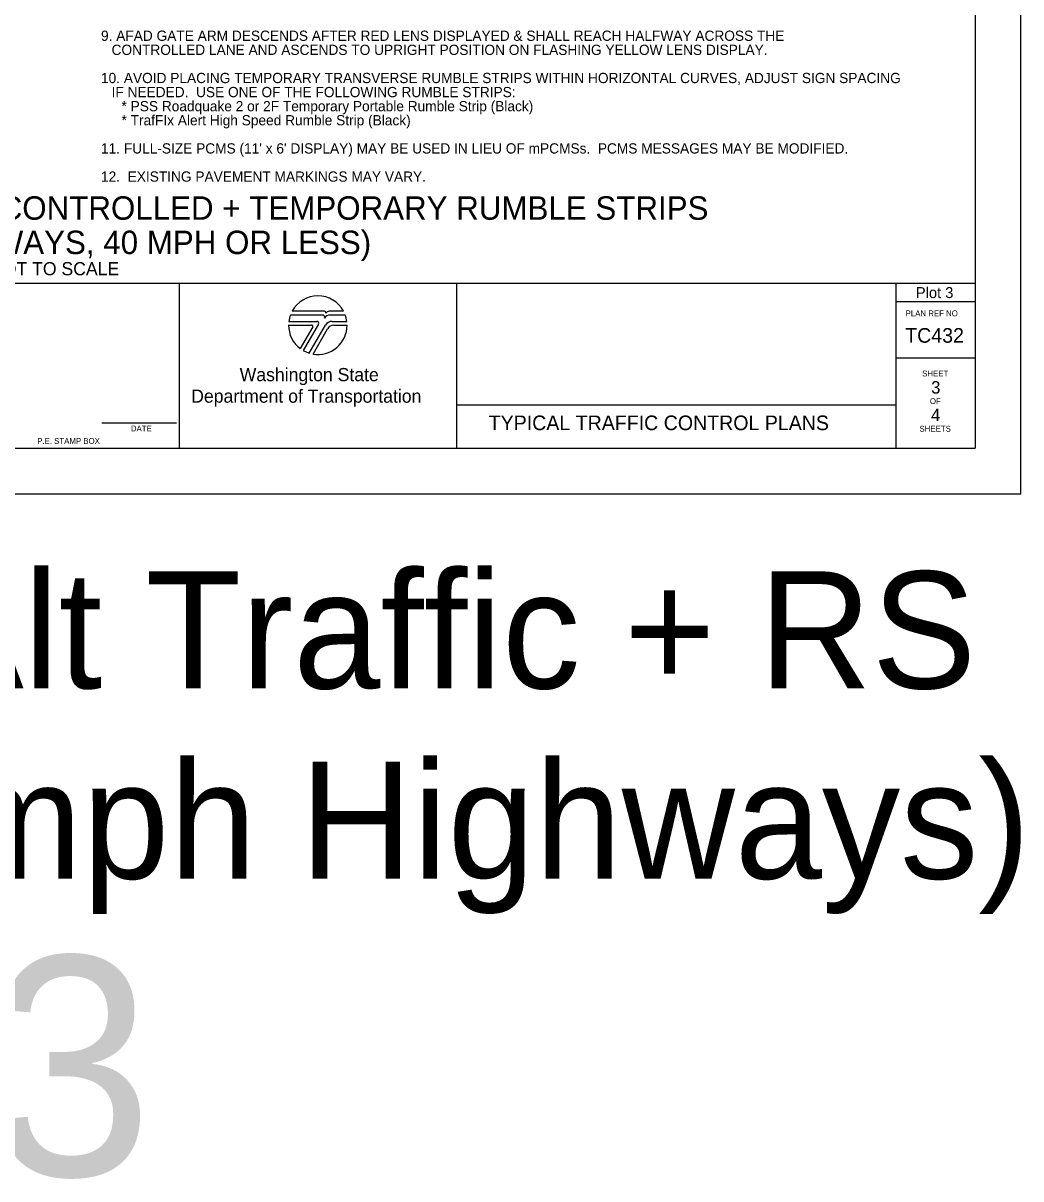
# Model space of a CAD drawing. Extents: x 99999.1 to 100095.7, y 99995 to 100010.7.
# Drawn here: x 100049.24 to 100056.06, y 99995.01 to 100002.9 of the extents above; entities that cross this region are included whole.
import ezdxf

# ---------------------------------------------------------------- set-up
doc = ezdxf.new("R2010")
doc.units = 0
for name, color, linetype in [('SH_DE_DetailHeading1Text', 7, 'Continuous'), ('SH_GI_GeneralNotesBodyText', 7, 'Continuous'), ('SH_GI_PlotLimits', 7, 'Continuous'), ('SH_GI_SheetBorder', 7, 'Continuous'), ('SH_GI_SheetLocationText', 7, 'Continuous'), ('SH_GI_SheetTextInCells', 7, 'Continuous'), ('SH_GI_TitleBlockText', 7, 'Continuous'), ('SH_GI_WSDOTLogo', 7, 'Continuous')]:
    doc.layers.add(name, color=color, linetype=linetype)

msp = doc.modelspace()

# ---------------------------------------------------------------- linework, layer by layer
at = {"layer": 'SH_GI_PlotLimits'}
msp.add_lwpolyline([(100039.0625, 99999.6875), (100056.0625, 99999.6875), (100056.0625, 100010.6875), (100039.0625, 100010.6875)], close=True, dxfattribs=at)
at = {"layer": 'SH_GI_SheetBorder'}
for p, q in [((100055.75, 100010.375), (100055.75, 100000)), ((100040, 100001.1259), (100055.75, 100001.1259)), ((100050.3089, 100001.1259), (100050.3089, 100000)), ((100052.2055, 100001.1259), (100052.2055, 100000)), ((100055.2079, 100001.1259), (100055.2079, 100000)), ((100055.2079, 100001.0008), (100055.75, 100001.0008)), ((100055.2079, 100000.6176), (100055.75, 100000.6176)), ((100052.2055, 100000.2955), (100055.2079, 100000.2955)), ((100049.7797, 100000.1733), (100050.2914, 100000.1733)), ((100040, 100000), (100055.75, 100000))]:
    msp.add_line(p, q, dxfattribs=at)
at = {"layer": 'SH_GI_WSDOTLogo'}
for p, q in [((100051.303, 100000.9354), (100051.0815, 100000.9354)), ((100051.433, 100000.9354), (100051.3351, 100000.9354)), ((100051.0572, 100000.84), (100051.2148, 100000.84)), ((100051.059, 100000.8661), (100051.2496, 100000.8661)), ((100051.2894, 100000.9094), (100051.0697, 100000.9094)), ((100051.261, 100000.8464), (100051.1567, 100000.6672)), ((100051.1989, 100000.6487), (100051.3089, 100000.839)), ((100051.343, 100000.9094), (100051.3429, 100000.9094)), ((100051.4448, 100000.9094), (100051.343, 100000.9094)), ((100051.3558, 100000.8661), (100051.4555, 100000.8661)), ((100051.3655, 100000.8394), (100051.4572, 100000.8394)), ((100051.222, 100000.8277), (100051.1364, 100000.6807)), ((100051.2244, 100000.6428), (100051.3242, 100000.8156))]:
    msp.add_line(p, q, dxfattribs=at)
for centre, radius, start, end in [((100051.2572, 100000.84), 0.2, 28.47865, 151.53204), ((100051.303, 100000.9263), 0.00903, 329.87418, 90.00328), ((100051.3352, 100000.9066), 0.0287, 90.00721, 148.16763), ((100051.2572, 100000.84), 0.2, 179.99864, 232.84327), ((100051.2572, 100000.84), 0.2, 159.69598, 172.50569), ((100051.2149, 100000.8318), 0.0082, 329.74356, 90), ((100051.2572, 100000.84), 0.2, 260.54554, 359.80857), ((100051.2497, 100000.853), 0.0131, 329.76834, 90), ((100051.2894, 100000.8946), 0.0148, 327.8418, 89.99855), ((100051.3429, 100000.861), 0.0484, 89.99529, 147.82376), ((100051.3558, 100000.8119), 0.0542, 90, 149.99738), ((100051.3654, 100000.7918), 0.0476, 90, 150.05432), ((100051.2572, 100000.84), 0.2, 7.49431, 20.29406), ((100051.2572, 100000.84), 0.2, 239.79292, 253.0448)]:
    msp.add_arc(centre, radius, start, end, dxfattribs=at)

# ---------------------------------------------------------------- texts
at = {"layer": 'SH_DE_DetailHeading1Text'}
for s, height, p in [('ALTERNATING 1-LANE, 2-WAY TRAFFIC: AFAD-CONTROLLED + TEMPORARY RUMBLE STRIPS', 0.16, (100044.2559, 100001.5606)), ('(HIGH VOLUME HIGHWAYS, 40 MPH OR LESS)', 0.16, (100046.8782, 100001.3259)), ('NOT TO SCALE', 0.09, (100049.0168, 100001.1809))]:
    msp.add_text(s, height=height, rotation=360, dxfattribs=at).set_placement(p)
at = {"layer": 'SH_GI_GeneralNotesBodyText'}
for s, p in [('9. AFAD GATE ARM DESCENDS AFTER RED LENS DISPLAYED & SHALL REACH HALFWAY ACROSS THE ', (100049.7751, 100002.7831)), ('CONTROLLED LANE AND ASCENDS TO UPRIGHT POSITION ON FLASHING YELLOW LENS DISPLAY.', (100049.8473, 100002.6868)), ('10. AVOID PLACING TEMPORARY TRANSVERSE RUMBLE STRIPS WITHIN HORIZONTAL CURVES, ADJUST SIGN SPACING ', (100049.7751, 100002.4943)), ('IF NEEDED.  USE ONE OF THE FOLLOWING RUMBLE STRIPS:', (100049.8473, 100002.3981)), ('* PSS Roadquake 2 or 2F Temporary Portable Rumble Strip (Black)', (100049.9151, 100002.3018)), ('* TrafFIx Alert High Speed Rumble Strip (Black)', (100049.9151, 100002.2056)), ("11. FULL-SIZE PCMS (11' x 6' DISPLAY) MAY BE USED IN LIEU OF mPCMSs.  PCMS MESSAGES MAY BE MODIFIED.", (100049.7751, 100002.0131)), ('12.  EXISTING PAVEMENT MARKINGS MAY VARY.', (100049.7751, 100001.8206))]:
    msp.add_text(s, height=0.07, rotation=360, dxfattribs=at).set_placement(p)
at = {"layer": 'SH_GI_SheetBorder'}
msp.add_text('PLAN REF NO', height=0.040032, dxfattribs=at).set_placement((100055.2747, 100000.9008))
at = {"layer": 'SH_GI_SheetLocationText'}
for s, height, p in [('Plot 3', 0.075, (100055.3447, 100001.025)), ('AFAD-Controlled Alt Traffic + RS', 0.8, (100040.1515, 99998.3571)), ('(High-Volume 40- mph Highways)', 0.8, (100040.0757, 99997.0571)), ('Plot 3', 1.5, (100045.0008, 99995.0267))]:
    msp.add_text(s, height=height, dxfattribs=at).set_placement(p)
at = {"layer": 'SH_GI_SheetTextInCells'}
for s, height, p in [('Washington State', 0.090072, (100050.7229, 100000.4571)), ('SHEET', 0.04003, (100055.3877, 100000.4896)), ('Department of Transportation', 0.090072, (100050.3916, 100000.3101)), ('OF', 0.04003, (100055.4406, 100000.3008)), ('DATE', 0.04003, (100049.9794, 100000.1141)), ('SHEETS', 0.04003, (100055.3698, 100000.112)), ('P.E. STAMP BOX', 0.040032, (100049.339, 100000.0286))]:
    msp.add_text(s, height=height, dxfattribs=at).set_placement(p)
at = {"layer": 'SH_GI_TitleBlockText'}
for s, height, p in [('TC432', 0.1, (100055.2718, 100000.72)), ('3', 0.085, (100055.4493, 100000.3723)), ('TYPICAL TRAFFIC CONTROL PLANS', 0.1, (100052.4251, 100000.1224)), ('4', 0.085, (100055.4485, 100000.1843))]:
    msp.add_text(s, height=height, dxfattribs=at).set_placement(p)

doc.saveas('drawing.dxf')
